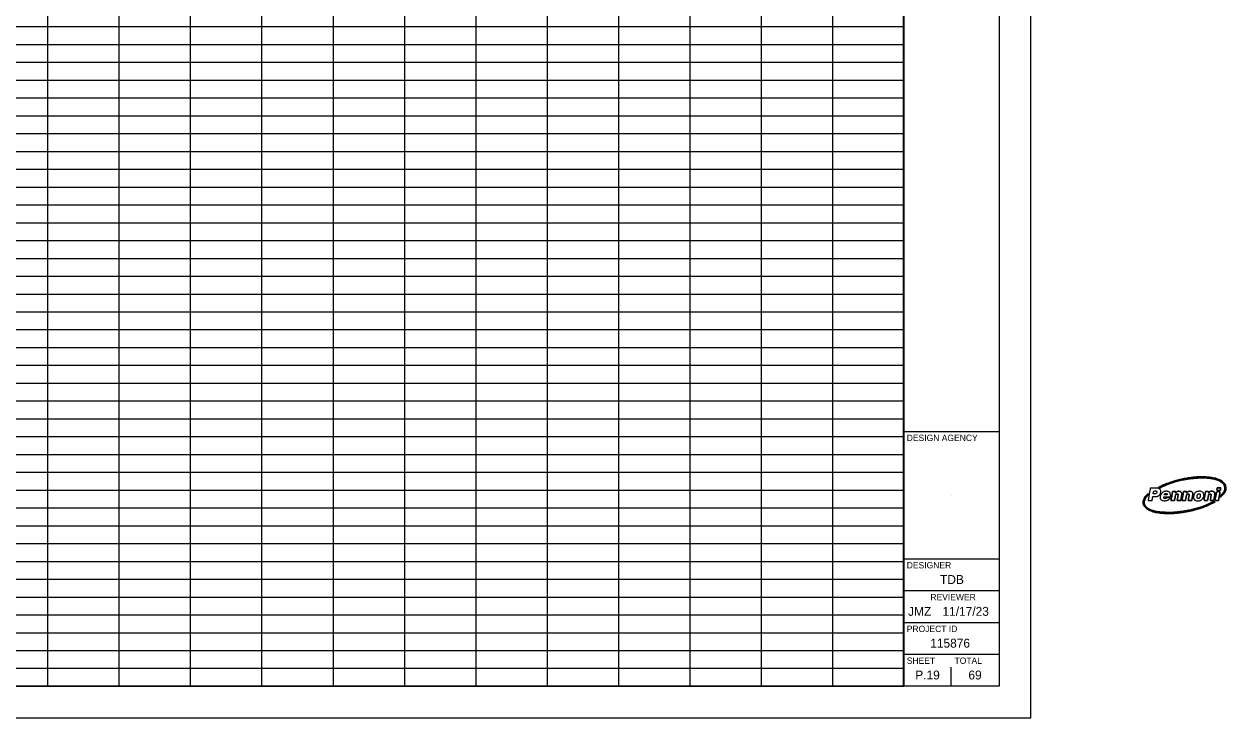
# Model space of a CAD drawing. Extents: x -0.1 to 36.9, y 0 to 22.
# Drawn here: x 18.07 to 36.94, y -0.02 to 10.88 of the extents above; entities that cross this region are included whole.
import ezdxf

# ---------------------------------------------------------------- set-up
doc = ezdxf.new("R2010")
doc.units = 0
for name, color, linetype in [('Default', 7, 'Continuous'), ('SH_Border', 7, 'Continuous'), ('SH_Cut_Line', 7, 'Continuous'), ('SH_Data', 7, 'Continuous')]:
    doc.layers.add(name, color=color, linetype=linetype)

msp = doc.modelspace()

# ---------------------------------------------------------------- linework, layer by layer
at = {"layer": 'Default'}
for p, q in [((18.439, 21.475), (18.439, 0.475)), ((19.559, 21.475), (19.559, 0.475)), ((20.679, 21.475), (20.679, 0.475)), ((21.799, 21.475), (21.799, 0.475)), ((22.919, 21.475), (22.919, 0.475)), ((24.039, 21.475), (24.039, 0.475)), ((25.159, 21.475), (25.159, 0.475)), ((26.279, 21.475), (26.279, 0.475)), ((27.399, 21.475), (27.399, 0.475)), ((28.519, 21.475), (28.519, 0.475)), ((29.639, 21.475), (29.639, 0.475)), ((30.759, 21.475), (30.759, 0.475)), ((31.879, 21.475), (31.879, 0.475)), ((1.376, 10.835), (31.879, 10.835)), ((1.376, 10.555), (31.879, 10.555)), ((1.376, 10.275), (31.879, 10.275)), ((1.376, 9.995), (31.879, 9.995)), ((1.376, 9.715), (31.879, 9.715)), ((1.376, 9.435), (31.879, 9.435)), ((1.376, 9.155), (31.879, 9.155)), ((1.376, 8.875), (31.879, 8.875)), ((1.376, 8.595), (31.879, 8.595)), ((1.376, 8.315), (31.879, 8.315)), ((1.376, 8.035), (31.879, 8.035)), ((1.376, 7.755), (31.879, 7.755)), ((1.376, 7.475), (31.879, 7.475)), ((1.376, 7.195), (31.879, 7.195)), ((1.376, 6.915), (31.879, 6.915)), ((1.376, 6.635), (31.879, 6.635)), ((1.376, 6.355), (31.879, 6.355)), ((1.376, 6.075), (31.879, 6.075)), ((1.376, 5.795), (31.879, 5.795)), ((1.376, 5.515), (31.879, 5.515)), ((1.376, 5.235), (31.879, 5.235)), ((1.376, 4.955), (31.879, 4.955)), ((1.376, 4.675), (31.879, 4.675)), ((1.376, 4.395), (31.879, 4.395)), ((1.376, 4.115), (31.879, 4.115)), ((1.376, 3.835), (31.879, 3.835)), ((1.376, 3.555), (31.879, 3.555)), ((1.376, 3.275), (31.879, 3.275)), ((1.376, 2.995), (31.879, 2.995)), ((1.376, 2.715), (31.879, 2.715)), ((1.376, 2.435), (31.879, 2.435)), ((1.376, 2.155), (31.879, 2.155)), ((1.376, 1.875), (31.879, 1.875)), ((1.376, 1.595), (31.879, 1.595)), ((1.376, 1.315), (31.879, 1.315)), ((1.376, 1.035), (31.879, 1.035)), ((1.376, 0.755), (31.879, 0.755)), ((1.376, 0.475), (31.879, 0.475))]:
    msp.add_line(p, q, dxfattribs=at)
at = {"layer": 'SH_Border'}
for p, q in [((31.876, 0.475), (31.876, 21.475)), ((31.876, 4.475), (33.376, 4.475)), ((36.017, 3.478), (35.966, 3.478)), ((31.876, 2.475), (33.376, 2.475)), ((31.876, 1.975), (33.376, 1.975)), ((31.876, 1.475), (33.376, 1.475)), ((31.876, 0.975), (33.376, 0.975))]:
    msp.add_line(p, q, dxfattribs=at)
msp.add_lwpolyline([(1.376, 21.475), (33.376, 21.475), (33.376, 0.475), (1.376, 0.475)], close=True, dxfattribs=at)
for points, degree in [([(35.887, 3.577), (35.875, 3.583), (35.861, 3.585), (35.847, 3.585), (35.816, 3.586), (35.784, 3.585), (35.752, 3.586), (35.75, 3.586), (35.749, 3.585), (35.749, 3.583), (35.745, 3.561), (35.741, 3.54), (35.737, 3.518), (35.731, 3.484), (35.725, 3.449), (35.719, 3.414), (35.718, 3.407), (35.717, 3.399), (35.715, 3.392)], 3), ([(35.876, 3.596), (35.883, 3.594), (35.889, 3.591), (35.895, 3.59), (35.897, 3.589), (35.899, 3.589), (35.901, 3.59), (35.93, 3.604), (35.959, 3.618), (35.988, 3.63), (36.029, 3.648), (36.071, 3.663), (36.114, 3.676), (36.156, 3.689), (36.198, 3.7), (36.241, 3.709), (36.281, 3.718), (36.321, 3.726), (36.362, 3.731), (36.394, 3.735), (36.426, 3.739), (36.458, 3.742), (36.483, 3.744), (36.508, 3.745), (36.533, 3.746), (36.589, 3.748), (36.643, 3.745), (36.698, 3.737), (36.728, 3.733), (36.757, 3.727), (36.786, 3.717), (36.821, 3.706), (36.855, 3.692), (36.883, 3.666), (36.898, 3.653), (36.909, 3.636), (36.915, 3.616), (36.919, 3.599), (36.921, 3.582), (36.918, 3.564), (36.915, 3.544), (36.905, 3.527), (36.892, 3.511), (36.88, 3.496), (36.866, 3.483), (36.851, 3.47), (36.85, 3.469), (36.848, 3.467), (36.848, 3.465), (36.846, 3.46), (36.846, 3.454), (36.845, 3.448), (36.844, 3.446), (36.844, 3.444), (36.844, 3.44), (36.867, 3.46), (36.89, 3.48), (36.909, 3.504), (36.918, 3.515), (36.925, 3.528), (36.93, 3.541), (36.937, 3.56), (36.938, 3.579), (36.935, 3.598), (36.931, 3.633), (36.916, 3.66), (36.89, 3.683), (36.866, 3.703), (36.838, 3.716), (36.809, 3.727), (36.772, 3.741), (36.733, 3.749), (36.694, 3.754), (36.659, 3.759), (36.624, 3.762), (36.589, 3.763), (36.532, 3.765), (36.476, 3.762), (36.42, 3.756), (36.389, 3.752), (36.358, 3.748), (36.328, 3.743), (36.282, 3.736), (36.238, 3.727), (36.193, 3.715), (36.133, 3.7), (36.073, 3.682), (36.015, 3.66), (35.974, 3.644), (35.934, 3.626), (35.895, 3.606), (35.889, 3.603), (35.883, 3.6), (35.876, 3.596)], 3), ([(35.876, 3.596), (35.883, 3.6), (35.889, 3.603), (35.895, 3.606), (35.934, 3.626), (35.974, 3.644), (36.015, 3.66), (36.073, 3.682), (36.133, 3.7), (36.193, 3.715), (36.238, 3.727), (36.282, 3.736), (36.328, 3.743), (36.358, 3.748), (36.389, 3.752), (36.42, 3.756), (36.476, 3.762), (36.532, 3.765), (36.589, 3.763), (36.624, 3.762), (36.659, 3.759), (36.694, 3.754), (36.733, 3.749), (36.772, 3.741), (36.809, 3.727), (36.838, 3.716), (36.866, 3.703), (36.89, 3.683), (36.916, 3.66), (36.931, 3.633), (36.935, 3.598), (36.938, 3.579), (36.937, 3.56), (36.93, 3.541), (36.925, 3.528), (36.918, 3.515), (36.909, 3.504), (36.89, 3.48), (36.867, 3.46), (36.844, 3.44), (36.844, 3.444), (36.844, 3.446), (36.845, 3.448), (36.846, 3.454), (36.846, 3.46), (36.848, 3.465), (36.848, 3.467), (36.85, 3.469), (36.851, 3.47), (36.866, 3.483), (36.88, 3.496), (36.892, 3.511), (36.905, 3.527), (36.915, 3.544), (36.918, 3.564), (36.921, 3.582), (36.919, 3.599), (36.915, 3.616), (36.909, 3.636), (36.898, 3.653), (36.883, 3.666), (36.855, 3.692), (36.821, 3.706), (36.786, 3.717), (36.757, 3.727), (36.728, 3.733), (36.698, 3.737), (36.643, 3.745), (36.589, 3.748), (36.533, 3.746), (36.508, 3.745), (36.483, 3.744), (36.458, 3.742), (36.426, 3.739), (36.394, 3.735), (36.362, 3.731), (36.321, 3.726), (36.281, 3.718), (36.241, 3.709), (36.198, 3.7), (36.156, 3.689), (36.114, 3.676), (36.071, 3.663), (36.029, 3.648), (35.988, 3.63), (35.959, 3.618), (35.93, 3.604), (35.901, 3.59), (35.899, 3.589), (35.897, 3.589), (35.895, 3.59), (35.889, 3.591), (35.883, 3.594), (35.876, 3.596)], 3), ([(36.855, 3.59), (36.853, 3.578), (36.851, 3.566), (36.849, 3.553), (36.849, 3.553), (36.847, 3.551), (36.846, 3.551), (36.829, 3.551), (36.811, 3.551), (36.793, 3.551), (36.795, 3.561), (36.797, 3.57), (36.798, 3.579), (36.799, 3.581), (36.799, 3.584), (36.799, 3.586), (36.799, 3.59), (36.801, 3.591), (36.804, 3.591), (36.82, 3.59), (36.836, 3.59), (36.851, 3.59), (36.852, 3.59), (36.854, 3.59), (36.855, 3.59)], 3), ([(36.855, 3.59), (36.854, 3.59), (36.852, 3.59), (36.851, 3.59), (36.836, 3.59), (36.82, 3.59), (36.804, 3.591), (36.801, 3.591), (36.799, 3.59), (36.799, 3.586), (36.799, 3.584), (36.799, 3.581), (36.798, 3.579), (36.797, 3.57), (36.795, 3.561), (36.793, 3.551), (36.811, 3.551), (36.829, 3.551), (36.846, 3.551), (36.847, 3.551), (36.849, 3.553), (36.849, 3.553), (36.851, 3.566), (36.853, 3.578), (36.855, 3.59)], 3), ([(36.764, 3.367), (36.764, 3.367), (36.764, 3.368), (36.764, 3.368), (36.754, 3.368), (36.744, 3.368), (36.734, 3.368), (36.731, 3.368), (36.728, 3.367), (36.726, 3.366), (36.689, 3.347), (36.651, 3.33), (36.612, 3.315), (36.554, 3.292), (36.495, 3.273), (36.435, 3.258), (36.391, 3.246), (36.348, 3.237), (36.304, 3.229), (36.28, 3.225), (36.255, 3.221), (36.23, 3.218), (36.204, 3.214), (36.179, 3.211), (36.153, 3.209), (36.129, 3.207), (36.105, 3.205), (36.08, 3.205), (36.052, 3.204), (36.024, 3.203), (35.996, 3.205), (35.965, 3.206), (35.934, 3.208), (35.903, 3.211), (35.865, 3.215), (35.828, 3.223), (35.791, 3.234), (35.76, 3.244), (35.729, 3.257), (35.703, 3.277), (35.686, 3.289), (35.672, 3.304), (35.663, 3.323), (35.651, 3.349), (35.652, 3.375), (35.662, 3.402), (35.672, 3.425), (35.686, 3.445), (35.702, 3.463), (35.708, 3.469), (35.713, 3.475), (35.714, 3.484), (35.714, 3.489), (35.716, 3.495), (35.717, 3.501), (35.715, 3.5), (35.714, 3.5), (35.714, 3.499), (35.704, 3.489), (35.694, 3.48), (35.685, 3.469), (35.666, 3.447), (35.65, 3.423), (35.642, 3.394), (35.637, 3.377), (35.636, 3.36), (35.639, 3.343), (35.644, 3.316), (35.658, 3.294), (35.678, 3.276), (35.701, 3.255), (35.727, 3.241), (35.756, 3.229), (35.803, 3.21), (35.852, 3.2), (35.902, 3.194), (35.933, 3.191), (35.964, 3.189), (35.995, 3.187), (36.037, 3.186), (36.08, 3.186), (36.122, 3.19), (36.156, 3.192), (36.19, 3.196), (36.224, 3.2), (36.255, 3.204), (36.286, 3.209), (36.316, 3.214), (36.371, 3.224), (36.424, 3.236), (36.477, 3.252), (36.523, 3.264), (36.567, 3.279), (36.611, 3.296), (36.654, 3.313), (36.696, 3.331), (36.737, 3.353), (36.746, 3.357), (36.755, 3.362), (36.764, 3.367)], 3), ([(36.764, 3.367), (36.755, 3.362), (36.746, 3.357), (36.737, 3.353), (36.696, 3.331), (36.654, 3.313), (36.611, 3.296), (36.567, 3.279), (36.523, 3.264), (36.477, 3.252), (36.424, 3.236), (36.371, 3.224), (36.316, 3.214), (36.286, 3.209), (36.255, 3.204), (36.224, 3.2), (36.19, 3.196), (36.156, 3.192), (36.122, 3.19), (36.08, 3.186), (36.037, 3.186), (35.995, 3.187), (35.964, 3.189), (35.933, 3.191), (35.902, 3.194), (35.852, 3.2), (35.803, 3.21), (35.756, 3.229), (35.727, 3.241), (35.701, 3.255), (35.678, 3.276), (35.658, 3.294), (35.644, 3.316), (35.639, 3.343), (35.636, 3.36), (35.637, 3.377), (35.642, 3.394), (35.65, 3.423), (35.666, 3.447), (35.685, 3.469), (35.694, 3.48), (35.704, 3.489), (35.714, 3.499), (35.714, 3.5), (35.715, 3.5), (35.717, 3.501), (35.716, 3.495), (35.714, 3.489), (35.714, 3.484), (35.713, 3.475), (35.708, 3.469), (35.702, 3.463), (35.686, 3.445), (35.672, 3.425), (35.662, 3.402), (35.652, 3.375), (35.651, 3.349), (35.663, 3.323), (35.672, 3.304), (35.686, 3.289), (35.703, 3.277), (35.729, 3.257), (35.76, 3.244), (35.791, 3.234), (35.828, 3.223), (35.865, 3.215), (35.903, 3.211), (35.934, 3.208), (35.965, 3.206), (35.996, 3.205), (36.024, 3.203), (36.052, 3.204), (36.08, 3.205), (36.105, 3.205), (36.129, 3.207), (36.153, 3.209), (36.179, 3.211), (36.204, 3.214), (36.23, 3.218), (36.255, 3.221), (36.28, 3.225), (36.304, 3.229), (36.348, 3.237), (36.391, 3.246), (36.435, 3.258), (36.495, 3.273), (36.554, 3.292), (36.612, 3.315), (36.651, 3.33), (36.689, 3.347), (36.726, 3.366), (36.728, 3.367), (36.731, 3.368), (36.734, 3.368), (36.744, 3.368), (36.754, 3.368), (36.764, 3.368), (36.764, 3.368), (36.764, 3.367), (36.764, 3.367)], 3), ([(35.715, 3.392), (35.716, 3.392), (35.717, 3.392), (35.717, 3.392), (35.737, 3.392), (35.756, 3.392), (35.776, 3.392), (35.778, 3.392), (35.778, 3.393), (35.779, 3.395), (35.781, 3.406), (35.783, 3.417), (35.785, 3.429), (35.786, 3.437), (35.787, 3.444), (35.789, 3.452)], 3), ([(35.789, 3.452), (35.796, 3.452), (35.803, 3.452), (35.81, 3.452), (35.823, 3.452), (35.836, 3.452), (35.849, 3.455), (35.865, 3.458), (35.88, 3.465), (35.892, 3.477), (35.907, 3.493), (35.913, 3.512), (35.914, 3.534), (35.914, 3.553), (35.905, 3.568), (35.887, 3.577)], 3), ([(35.797, 3.497), (35.799, 3.511), (35.801, 3.525), (35.804, 3.538), (35.804, 3.539), (35.805, 3.54), (35.806, 3.54), (35.818, 3.54), (35.829, 3.542), (35.84, 3.538), (35.851, 3.535), (35.854, 3.529), (35.852, 3.518)], 3), ([(35.852, 3.518), (35.85, 3.506), (35.841, 3.498), (35.829, 3.497), (35.818, 3.497), (35.808, 3.497), (35.797, 3.497)], 3), ([(36.068, 3.483), (36.064, 3.508), (36.051, 3.525), (36.027, 3.532), (36.014, 3.537), (36.001, 3.537), (35.987, 3.536), (35.965, 3.533), (35.946, 3.524), (35.931, 3.507), (35.917, 3.493), (35.909, 3.475), (35.907, 3.454), (35.903, 3.425), (35.916, 3.401), (35.945, 3.392), (35.961, 3.387), (35.977, 3.387), (35.993, 3.389), (36.011, 3.391), (36.027, 3.397), (36.041, 3.409), (36.049, 3.416), (36.055, 3.424), (36.06, 3.434)], 3), ([(36.06, 3.434), (36.042, 3.434), (36.026, 3.434), (36.009, 3.434), (36.008, 3.434), (36.007, 3.433), (36.006, 3.432), (36.001, 3.429), (35.998, 3.425), (35.993, 3.423), (35.977, 3.417), (35.96, 3.426), (35.96, 3.445), (35.961, 3.449), (35.962, 3.45), (35.966, 3.45), (35.998, 3.45), (36.03, 3.45), (36.062, 3.45), (36.064, 3.45), (36.065, 3.45), (36.067, 3.45)], 3), ([(35.966, 3.478), (35.968, 3.49), (35.977, 3.5), (35.989, 3.502), (35.995, 3.503), (36.001, 3.503), (36.007, 3.5), (36.014, 3.496), (36.018, 3.488), (36.017, 3.478)], 3), ([(36.067, 3.45), (36.069, 3.461), (36.07, 3.472), (36.068, 3.483)], 2), ([(36.074, 3.391), (36.075, 3.39), (36.075, 3.39), (36.076, 3.39), (36.093, 3.39), (36.11, 3.39), (36.127, 3.39), (36.129, 3.39), (36.13, 3.392), (36.13, 3.393), (36.132, 3.401), (36.133, 3.41), (36.134, 3.418), (36.138, 3.435), (36.14, 3.453), (36.144, 3.471), (36.146, 3.48), (36.151, 3.488), (36.161, 3.49), (36.174, 3.494), (36.187, 3.491), (36.185, 3.472), (36.184, 3.457), (36.181, 3.443), (36.178, 3.429), (36.176, 3.416), (36.174, 3.404), (36.172, 3.391), (36.172, 3.39), (36.173, 3.39), (36.173, 3.39), (36.19, 3.39), (36.207, 3.39), (36.224, 3.39), (36.227, 3.39), (36.227, 3.392), (36.228, 3.394), (36.232, 3.418), (36.236, 3.441), (36.24, 3.465), (36.242, 3.478), (36.245, 3.49), (36.243, 3.502), (36.241, 3.518), (36.231, 3.53), (36.216, 3.533), (36.194, 3.539), (36.174, 3.535), (36.157, 3.52), (36.153, 3.517), (36.15, 3.513), (36.146, 3.51), (36.147, 3.517), (36.148, 3.524), (36.149, 3.532), (36.133, 3.532), (36.117, 3.532), (36.101, 3.531), (36.1, 3.531), (36.099, 3.53), (36.098, 3.529), (36.097, 3.525), (36.097, 3.521), (36.096, 3.516), (36.091, 3.486), (36.085, 3.455), (36.08, 3.425), (36.078, 3.413), (36.076, 3.402), (36.074, 3.391)], 3), ([(36.074, 3.391), (36.076, 3.402), (36.078, 3.413), (36.08, 3.425), (36.085, 3.455), (36.091, 3.486), (36.096, 3.516), (36.097, 3.521), (36.097, 3.525), (36.098, 3.529), (36.099, 3.53), (36.1, 3.531), (36.101, 3.531), (36.117, 3.532), (36.133, 3.532), (36.149, 3.532), (36.148, 3.524), (36.147, 3.517), (36.146, 3.51), (36.15, 3.513), (36.153, 3.517), (36.157, 3.52), (36.174, 3.535), (36.194, 3.539), (36.216, 3.533), (36.231, 3.53), (36.241, 3.518), (36.243, 3.502), (36.245, 3.49), (36.242, 3.478), (36.24, 3.465), (36.236, 3.441), (36.232, 3.418), (36.228, 3.394), (36.227, 3.392), (36.227, 3.39), (36.224, 3.39), (36.207, 3.39), (36.19, 3.39), (36.173, 3.39), (36.173, 3.39), (36.172, 3.39), (36.172, 3.391), (36.174, 3.404), (36.176, 3.416), (36.178, 3.429), (36.181, 3.443), (36.184, 3.457), (36.185, 3.472), (36.187, 3.491), (36.174, 3.494), (36.161, 3.49), (36.151, 3.488), (36.146, 3.48), (36.144, 3.471), (36.14, 3.453), (36.138, 3.435), (36.134, 3.418), (36.133, 3.41), (36.132, 3.401), (36.13, 3.393), (36.13, 3.392), (36.129, 3.39), (36.127, 3.39), (36.11, 3.39), (36.093, 3.39), (36.076, 3.39), (36.075, 3.39), (36.075, 3.39), (36.074, 3.391)], 3), ([(36.247, 3.391), (36.248, 3.39), (36.248, 3.39), (36.248, 3.39), (36.266, 3.39), (36.283, 3.39), (36.3, 3.39), (36.301, 3.39), (36.303, 3.392), (36.303, 3.393), (36.306, 3.41), (36.309, 3.427), (36.312, 3.444), (36.314, 3.454), (36.316, 3.465), (36.319, 3.475), (36.323, 3.488), (36.335, 3.494), (36.348, 3.491), (36.354, 3.49), (36.357, 3.486), (36.358, 3.48), (36.358, 3.477), (36.359, 3.474), (36.358, 3.471), (36.357, 3.46), (36.355, 3.448), (36.353, 3.437), (36.35, 3.422), (36.347, 3.406), (36.345, 3.391), (36.345, 3.391), (36.345, 3.39), (36.345, 3.39), (36.363, 3.39), (36.38, 3.39), (36.398, 3.39), (36.399, 3.39), (36.4, 3.392), (36.4, 3.393), (36.405, 3.416), (36.409, 3.438), (36.412, 3.46), (36.414, 3.472), (36.416, 3.484), (36.416, 3.497), (36.416, 3.512), (36.41, 3.525), (36.395, 3.531), (36.374, 3.539), (36.354, 3.537), (36.336, 3.525), (36.33, 3.52), (36.325, 3.515), (36.319, 3.51), (36.32, 3.518), (36.321, 3.524), (36.322, 3.532), (36.306, 3.532), (36.29, 3.532), (36.274, 3.532), (36.271, 3.532), (36.272, 3.53), (36.271, 3.528), (36.267, 3.504), (36.263, 3.48), (36.259, 3.457), (36.255, 3.435), (36.251, 3.413), (36.247, 3.391)], 3), ([(36.247, 3.391), (36.251, 3.413), (36.255, 3.435), (36.259, 3.457), (36.263, 3.48), (36.267, 3.504), (36.271, 3.528), (36.272, 3.53), (36.271, 3.532), (36.274, 3.532), (36.29, 3.532), (36.306, 3.532), (36.322, 3.532), (36.321, 3.524), (36.32, 3.518), (36.319, 3.51), (36.325, 3.515), (36.33, 3.52), (36.336, 3.525), (36.354, 3.537), (36.374, 3.539), (36.395, 3.531), (36.41, 3.525), (36.416, 3.512), (36.416, 3.497), (36.416, 3.484), (36.414, 3.472), (36.412, 3.46), (36.409, 3.438), (36.405, 3.416), (36.4, 3.393), (36.4, 3.392), (36.399, 3.39), (36.398, 3.39), (36.38, 3.39), (36.363, 3.39), (36.345, 3.39), (36.345, 3.39), (36.345, 3.391), (36.345, 3.391), (36.347, 3.406), (36.35, 3.422), (36.353, 3.437), (36.355, 3.448), (36.357, 3.46), (36.358, 3.471), (36.359, 3.474), (36.358, 3.477), (36.358, 3.48), (36.357, 3.486), (36.354, 3.49), (36.348, 3.491), (36.335, 3.494), (36.323, 3.488), (36.319, 3.475), (36.316, 3.465), (36.314, 3.454), (36.312, 3.444), (36.309, 3.427), (36.306, 3.41), (36.303, 3.393), (36.303, 3.392), (36.301, 3.39), (36.3, 3.39), (36.283, 3.39), (36.266, 3.39), (36.248, 3.39), (36.248, 3.39), (36.248, 3.39), (36.247, 3.391)], 3), ([(36.59, 3.483), (36.589, 3.505), (36.578, 3.521), (36.557, 3.529), (36.538, 3.537), (36.518, 3.537), (36.498, 3.533), (36.474, 3.528), (36.455, 3.516), (36.442, 3.495), (36.441, 3.493), (36.439, 3.49), (36.438, 3.488), (36.437, 3.486), (36.436, 3.484), (36.435, 3.482), (36.43, 3.471), (36.428, 3.459), (36.427, 3.447), (36.427, 3.445), (36.427, 3.442), (36.427, 3.44), (36.428, 3.432), (36.429, 3.425), (36.432, 3.419), (36.433, 3.418), (36.433, 3.416), (36.434, 3.415), (36.434, 3.414), (36.435, 3.413), (36.436, 3.412), (36.438, 3.409), (36.441, 3.405), (36.444, 3.402), (36.446, 3.401), (36.448, 3.399), (36.45, 3.398), (36.451, 3.397), (36.451, 3.397), (36.452, 3.397), (36.453, 3.396), (36.454, 3.395), (36.456, 3.395), (36.457, 3.394), (36.459, 3.393), (36.461, 3.392), (36.472, 3.388), (36.484, 3.386), (36.496, 3.386)], 3), ([(36.483, 3.446), (36.484, 3.463), (36.486, 3.476), (36.496, 3.488), (36.501, 3.494), (36.507, 3.498), (36.516, 3.498), (36.524, 3.498), (36.53, 3.495), (36.532, 3.486), (36.534, 3.48), (36.534, 3.473), (36.534, 3.466)], 3), ([(36.534, 3.466), (36.533, 3.456), (36.53, 3.446), (36.525, 3.437), (36.519, 3.427), (36.51, 3.422), (36.499, 3.424), (36.492, 3.425), (36.488, 3.428), (36.486, 3.435), (36.484, 3.439), (36.484, 3.444), (36.483, 3.446)], 3), ([(36.496, 3.386), (36.503, 3.386), (36.51, 3.387), (36.517, 3.388), (36.537, 3.392), (36.554, 3.4), (36.567, 3.414), (36.584, 3.434), (36.592, 3.457), (36.59, 3.483)], 3), ([(36.618, 3.531), (36.61, 3.484), (36.601, 3.438), (36.593, 3.39), (36.612, 3.39), (36.63, 3.39), (36.649, 3.39), (36.651, 3.405), (36.654, 3.419), (36.656, 3.433), (36.659, 3.446), (36.661, 3.459), (36.664, 3.471), (36.667, 3.485), (36.676, 3.492), (36.69, 3.492), (36.699, 3.491), (36.704, 3.487), (36.704, 3.478), (36.705, 3.475), (36.705, 3.472), (36.704, 3.469), (36.701, 3.45), (36.698, 3.431), (36.694, 3.412), (36.693, 3.405), (36.692, 3.398), (36.691, 3.39), (36.71, 3.39), (36.728, 3.39), (36.746, 3.39), (36.746, 3.392), (36.747, 3.393), (36.747, 3.394), (36.751, 3.415), (36.754, 3.437), (36.758, 3.458), (36.76, 3.472), (36.763, 3.485), (36.762, 3.5), (36.761, 3.516), (36.752, 3.528), (36.737, 3.533), (36.712, 3.54), (36.69, 3.534), (36.671, 3.516), (36.67, 3.514), (36.668, 3.512), (36.666, 3.51), (36.665, 3.51), (36.665, 3.51), (36.665, 3.511), (36.666, 3.517), (36.667, 3.524), (36.669, 3.531), (36.651, 3.531), (36.635, 3.531), (36.618, 3.531)], 3), ([(36.618, 3.531), (36.635, 3.531), (36.651, 3.531), (36.669, 3.531), (36.667, 3.524), (36.666, 3.517), (36.665, 3.511), (36.665, 3.51), (36.665, 3.51), (36.666, 3.51), (36.668, 3.512), (36.67, 3.514), (36.671, 3.516), (36.69, 3.534), (36.712, 3.54), (36.737, 3.533), (36.752, 3.528), (36.761, 3.516), (36.762, 3.5), (36.763, 3.485), (36.76, 3.472), (36.758, 3.458), (36.754, 3.437), (36.751, 3.415), (36.747, 3.394), (36.747, 3.393), (36.746, 3.392), (36.746, 3.39), (36.728, 3.39), (36.71, 3.39), (36.691, 3.39), (36.692, 3.398), (36.693, 3.405), (36.694, 3.412), (36.698, 3.431), (36.701, 3.45), (36.704, 3.469), (36.705, 3.472), (36.705, 3.475), (36.704, 3.478), (36.704, 3.487), (36.699, 3.491), (36.69, 3.492), (36.676, 3.492), (36.667, 3.485), (36.664, 3.471), (36.661, 3.459), (36.659, 3.446), (36.656, 3.433), (36.654, 3.419), (36.651, 3.405), (36.649, 3.39), (36.63, 3.39), (36.612, 3.39), (36.593, 3.39), (36.601, 3.438), (36.61, 3.484), (36.618, 3.531)], 3), ([(36.821, 3.392), (36.802, 3.392), (36.784, 3.392), (36.765, 3.392), (36.774, 3.439), (36.782, 3.485), (36.79, 3.532), (36.808, 3.532), (36.826, 3.532), (36.845, 3.532), (36.837, 3.485), (36.829, 3.439), (36.821, 3.392)], 3), ([(36.821, 3.392), (36.829, 3.439), (36.837, 3.485), (36.845, 3.532), (36.826, 3.532), (36.808, 3.532), (36.79, 3.532), (36.782, 3.485), (36.774, 3.439), (36.765, 3.392), (36.784, 3.392), (36.802, 3.392), (36.821, 3.392)], 3)]:
    msp.add_open_spline(points, degree=degree, dxfattribs=at)
at = {"layer": 'SH_Cut_Line'}
msp.add_lwpolyline([(-0.124, -0.025), (33.876, -0.025), (33.876, 21.975), (-0.124, 21.975)], close=True, dxfattribs=at)
at = {"layer": 'SH_Data'}
for p, q in [((32.626, 3.475), (32.626, 3.475)), ((32.626, 0.475), (32.626, 0.775)), ((32.251, 0.65), (32.251, 0.65))]:
    msp.add_line(p, q, dxfattribs=at)

# ---------------------------------------------------------------- texts
for s, height, p in [('DESIGN AGENCY', 0.1, (31.926, 4.325)), ('DESIGNER', 0.1, (31.926, 2.325)), ('TDB', 0.14, (32.449, 2.08)), ('REVIEWER', 0.1, (32.297, 1.825)), ('JMZ', 0.14, (31.947, 1.58)), ('11/17/23', 0.14, (32.487, 1.58)), ('PROJECT ID', 0.1, (31.926, 1.325)), ('115876', 0.14, (32.295, 1.08)), ('SHEET', 0.1, (31.926, 0.825)), ('TOTAL', 0.1, (32.676, 0.825)), ('P.19', 0.14, (32.06, 0.58)), ('69', 0.14, (32.894, 0.58))]:
    msp.add_text(s, height=height, dxfattribs=at).set_placement(p)

doc.saveas('drawing.dxf')
